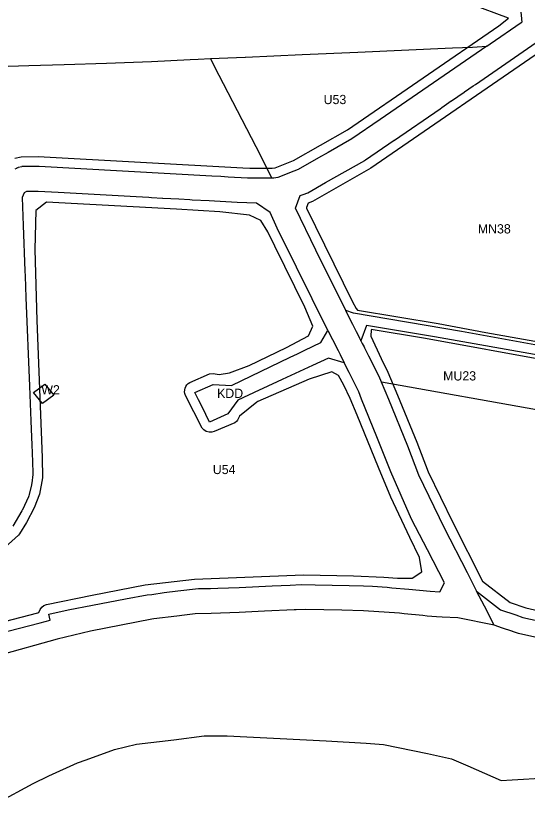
# Model space of a CAD drawing. Extents: x 7428103 to 7431580, y 5545880 to 5549002.
# Drawn here: x 7429910.1 to 7430217.3, y 5546647.9 to 5547123.1 of the extents above; entities that cross this region are included whole.
import ezdxf

# ---------------------------------------------------------------- set-up
doc = ezdxf.new("R2010")
doc.units = 0
for name, color, linetype in [('CZ_L_linie rozgraniczające tereny o różnym przeznaczeniu oraz różnych warunkach ich zabudowy i zagospodarowania', 7, 'Continuous'), ('CZ_L_maksymalne nieprzekraczalne linie zabudowy', 7, 'Continuous'), ('CZ_L_opisy_linie rozgraniczające tereny o różnym przeznaczeniu oraz różnych warunkach ich zabudowy i zagospodarowania', 7, 'Continuous')]:
    doc.layers.add(name, color=color, linetype=linetype)

msp = doc.modelspace()

# ---------------------------------------------------------------- linework, layer by layer
at = {"layer": 'CZ_L_linie rozgraniczające tereny o różnym przeznaczeniu oraz różnych warunkach ich zabudowy i zagospodarowania'}
for p, q in [((7430214.07, 5547121.48), (7430213.66, 5547125.26)), ((7430214.13, 5547120.94), (7430214.07, 5547121.48)), ((7430214.29, 5547119.51), (7430214.13, 5547120.94)), ((7430195.04, 5547106.24), (7430213.63, 5547119.05)), ((7430213.63, 5547119.05), (7430214.29, 5547119.51)), ((7430186.16, 5547081.91), (7430227.89, 5547110.67)), ((7430193.08, 5547104.9), (7430195.04, 5547106.24)), ((7430082.13, 5547099.87), (7430115.61, 5547101.33)), ((7430115.61, 5547101.33), (7430172.37, 5547103.82)), ((7430192.96, 5547104.82), (7430128.96, 5547060.72)), ((7430172.37, 5547103.82), (7430184.45, 5547104.35)), ((7430184.45, 5547104.35), (7430192.96, 5547104.82)), ((7430192.96, 5547104.82), (7430193.08, 5547104.9)), ((7429991.56, 5547095.77), (7430014.76, 5547096.83)), ((7430014.73, 5547096.88), (7430019.55, 5547097.14)), ((7430014.76, 5547096.83), (7430014.73, 5547096.88)), ((7430019.55, 5547097.14), (7430026.94, 5547097.46)), ((7430026.94, 5547097.46), (7430047.84, 5547098.37)), ((7430026.94, 5547097.46), (7430029.2, 5547092.87)), ((7430047.84, 5547098.37), (7430047.98, 5547098.37)), ((7430047.98, 5547098.37), (7430082.13, 5547099.87)), ((7429876.37, 5547092.06), (7429917.87, 5547093.18)), ((7429917.87, 5547093.18), (7429939.04, 5547093.84)), ((7429939.04, 5547093.84), (7429964.6, 5547094.63)), ((7429964.6, 5547094.63), (7429991.56, 5547095.77)), ((7430029.2, 5547092.87), (7430037.4, 5547077.05)), ((7430184.86, 5547081.02), (7430186.16, 5547081.91)), ((7430037.4, 5547077.05), (7430054.22, 5547044.6)), ((7430171.79, 5547072.03), (7430179.45, 5547077.3)), ((7430179.45, 5547077.3), (7430179.47, 5547077.31)), ((7430179.47, 5547077.31), (7430179.55, 5547077.36)), ((7430179.55, 5547077.36), (7430184.86, 5547081.02)), ((7430164.93, 5547067.29), (7430166.04, 5547068.05)), ((7430166.04, 5547068.05), (7430171.67, 5547071.93)), ((7430171.67, 5547071.93), (7430171.79, 5547072.03)), ((7430137.47, 5547048.36), (7430164.93, 5547067.29)), ((7430128.96, 5547060.72), (7430111.97, 5547049.08)), ((7430111.97, 5547049.08), (7430097.71, 5547040.99)), ((7430054.22, 5547044.6), (7430063.83, 5547025.55)), ((7430120.19, 5547036.53), (7430137.45, 5547048.35)), ((7430137.45, 5547048.35), (7430137.46, 5547048.35)), ((7430137.46, 5547048.35), (7430137.47, 5547048.36)), ((7430097.71, 5547040.99), (7430091.96, 5547037.73)), ((7430091.96, 5547037.73), (7430079.67, 5547030.76)), ((7430096.17, 5547022.87), (7430119.65, 5547036.19)), ((7430119.65, 5547036.19), (7430119.71, 5547036.24)), ((7430119.71, 5547036.24), (7430119.84, 5547036.32)), ((7430119.84, 5547036.32), (7430119.86, 5547036.33)), ((7430119.86, 5547036.33), (7430120.08, 5547036.46)), ((7430120.08, 5547036.46), (7430120.11, 5547036.48)), ((7430120.11, 5547036.48), (7430120.19, 5547036.53)), ((7429910.5, 5547031.42), (7429909.53, 5547030.84)), ((7429910.56, 5547031.45), (7429910.5, 5547031.42)), ((7429910.57, 5547031.46), (7429910.56, 5547031.45)), ((7429911.15, 5547031.77), (7429910.57, 5547031.46)), ((7429911.19, 5547031.78), (7429911.15, 5547031.77)), ((7429911.2, 5547031.79), (7429911.19, 5547031.78)), ((7429911.21, 5547031.8), (7429911.2, 5547031.79)), ((7429911.22, 5547031.81), (7429911.21, 5547031.8)), ((7429911.5, 5547031.91), (7429911.22, 5547031.81)), ((7429913.73, 5547032.44), (7429911.5, 5547031.91)), ((7429913.78, 5547032.45), (7429913.73, 5547032.44)), ((7429914.07, 5547032.5), (7429913.78, 5547032.45)), ((7429914.17, 5547032.49), (7429914.07, 5547032.5)), ((7429914.24, 5547032.5), (7429914.17, 5547032.49)), ((7429914.26, 5547032.5), (7429914.24, 5547032.5)), ((7429914.28, 5547032.5), (7429914.26, 5547032.5)), ((7429923.55, 5547032.61), (7429914.28, 5547032.5)), ((7429923.58, 5547032.61), (7429923.55, 5547032.61)), ((7429923.6, 5547032.6), (7429923.58, 5547032.61)), ((7429923.61, 5547032.61), (7429923.6, 5547032.6)), ((7429923.63, 5547032.61), (7429923.61, 5547032.61)), ((7429923.65, 5547032.61), (7429923.63, 5547032.61)), ((7429923.99, 5547032.6), (7429923.65, 5547032.61)), ((7429924, 5547032.6), (7429923.99, 5547032.6)), ((7429924.06, 5547032.6), (7429924, 5547032.6)), ((7430027.9, 5547026.75), (7429924.06, 5547032.6)), ((7430077.06, 5547029.67), (7430067.54, 5547025.98)), ((7430079.66, 5547030.75), (7430077.06, 5547029.67)), ((7430079.67, 5547030.76), (7430079.66, 5547030.75)), ((7430033.22, 5547026.45), (7430027.9, 5547026.75)), ((7430037.55, 5547026.21), (7430033.22, 5547026.45)), ((7430049.34, 5547025.55), (7430037.55, 5547026.21)), ((7430049.38, 5547025.54), (7430049.34, 5547025.55)), ((7430063.83, 5547025.55), (7430049.38, 5547025.54)), ((7430065.12, 5547025.55), (7430063.83, 5547025.55)), ((7430067.54, 5547025.98), (7430065.12, 5547025.55)), ((7430085.45, 5547016.79), (7430096.17, 5547022.87)), ((7429915.08, 5547016.67), (7429913.85, 5547013.94)), ((7429916.5, 5547017.53), (7429915.08, 5547016.67)), ((7429923.47, 5547017.61), (7429916.5, 5547017.53)), ((7429935.42, 5547016.94), (7429923.47, 5547017.61)), ((7429982.3, 5547014.3), (7429935.42, 5547016.94)), ((7430080.91, 5547015.06), (7430082.71, 5547015.78)), ((7430082.71, 5547015.78), (7430085.42, 5547016.77)), ((7430085.42, 5547016.77), (7430085.45, 5547016.79)), ((7429913.85, 5547013.94), (7429914.5, 5546997.16)), ((7429990.05, 5547013.86), (7429982.3, 5547014.3)), ((7429991.68, 5547013.77), (7429990.05, 5547013.86)), ((7429998.21, 5547013.4), (7429991.68, 5547013.77)), ((7429998.32, 5547013.38), (7429998.21, 5547013.4)), ((7430007.94, 5547012.84), (7429998.32, 5547013.38)), ((7430008.08, 5547012.84), (7430007.94, 5547012.84)), ((7430008.09, 5547012.85), (7430008.08, 5547012.84)), ((7430014.65, 5547012.48), (7430008.09, 5547012.85)), ((7430015.98, 5547012.4), (7430014.65, 5547012.48)), ((7430026.16, 5547011.83), (7430015.98, 5547012.4)), ((7430029.43, 5547011.64), (7430026.16, 5547011.83)), ((7430043.05, 5547010.88), (7430029.43, 5547011.64)), ((7430054.67, 5547010.42), (7430043.05, 5547010.88)), ((7430078.03, 5547007.45), (7430080.91, 5547015.06)), ((7430062.88, 5547004.79), (7430054.67, 5547010.42)), ((7430090.32, 5546982.18), (7430078.03, 5547007.45)), ((7430067.03, 5546995.38), (7430062.88, 5547004.79)), ((7429914.5, 5546997.16), (7429915.56, 5546969.84)), ((7430078.67, 5546971.92), (7430067.03, 5546995.38)), ((7430106.9, 5546948.83), (7430090.32, 5546982.18)), ((7429915.56, 5546969.84), (7429915.69, 5546966.56)), ((7430097.58, 5546934.01), (7430078.67, 5546971.92)), ((7429915.69, 5546966.56), (7429916.18, 5546953.87)), ((7429916.18, 5546953.87), (7429918.25, 5546900.55)), ((7430108.26, 5546946.1), (7430106.9, 5546948.83)), ((7430108.29, 5546946.04), (7430108.26, 5546946.1)), ((7430111.58, 5546939.45), (7430108.29, 5546946.04)), ((7430112.94, 5546944.31), (7430108.29, 5546946.04)), ((7430177.87, 5546933.33), (7430112.94, 5546944.31)), ((7430112.57, 5546937.47), (7430111.58, 5546939.45)), ((7430113.7, 5546935.2), (7430112.57, 5546937.47)), ((7430114.74, 5546933.12), (7430113.7, 5546935.2)), ((7430120.69, 5546936.95), (7430117.39, 5546927.81)), ((7430161.61, 5546930.19), (7430120.69, 5546936.95)), ((7430093.22, 5546926.67), (7430097.58, 5546934.01)), ((7430097.58, 5546934.01), (7430100.29, 5546928.57)), ((7430115.47, 5546931.65), (7430114.74, 5546933.12)), ((7430116.7, 5546929.2), (7430115.47, 5546931.65)), ((7430271.15, 5546910.68), (7430161.61, 5546930.19)), ((7430228.48, 5546924.09), (7430177.87, 5546933.33)), ((7430083.62, 5546922.03), (7430093.22, 5546926.67)), ((7430100.29, 5546928.57), (7430103.63, 5546921.89)), ((7430117.33, 5546927.94), (7430116.7, 5546929.2)), ((7430117.39, 5546927.81), (7430117.33, 5546927.94)), ((7430117.39, 5546927.81), (7430118.21, 5546926.18)), ((7430118.21, 5546926.18), (7430119.28, 5546924.05)), ((7430079.3, 5546919.94), (7430083.62, 5546922.03)), ((7430103.63, 5546921.89), (7430104.83, 5546919.49)), ((7430119.28, 5546924.05), (7430119.55, 5546923.52)), ((7430119.55, 5546923.52), (7430120.8, 5546921.04)), ((7430120.8, 5546921.04), (7430121.95, 5546918.75)), ((7430039.66, 5546900.79), (7430074.97, 5546917.85)), ((7430074.97, 5546917.85), (7430079.3, 5546919.94)), ((7430097.86, 5546917.23), (7430088.26, 5546912.8)), ((7430107.35, 5546914.43), (7430097.86, 5546917.23)), ((7430104.83, 5546919.49), (7430107.35, 5546914.43)), ((7430121.95, 5546918.75), (7430128.07, 5546906.56)), ((7430088.26, 5546912.8), (7430070.05, 5546904.42)), ((7430110.24, 5546908.63), (7430107.35, 5546914.43)), ((7430116.1, 5546896.98), (7430110.24, 5546908.63)), ((7430128.07, 5546906.56), (7430129.53, 5546903.08)), ((7429920.78, 5546896.73), (7429927.49, 5546901.71)), ((7429927.49, 5546901.71), (7429932.96, 5546895.13)), ((7430017.67, 5546896.68), (7430028.68, 5546901.46)), ((7430028.68, 5546901.46), (7430039.66, 5546900.79)), ((7430070.05, 5546904.42), (7430058.53, 5546899.11)), ((7430129.53, 5546903.08), (7430129.8, 5546903.11)), ((7430129.53, 5546903.08), (7430133.9, 5546892.72)), ((7430129.8, 5546903.11), (7430285.61, 5546875.17)), ((7429918.25, 5546900.55), (7429919.06, 5546879.69)), ((7429926.08, 5546890.04), (7429920.78, 5546896.73)), ((7430019.89, 5546892.2), (7430017.67, 5546896.68)), ((7430056.31, 5546898.09), (7430043.41, 5546892.15)), ((7430058.53, 5546899.11), (7430056.31, 5546898.09)), ((7430117.83, 5546892.59), (7430116.1, 5546896.98)), ((7429932.96, 5546895.13), (7429926.08, 5546890.04)), ((7430023.73, 5546884.42), (7430019.89, 5546892.2)), ((7430043.41, 5546892.15), (7430037.36, 5546883.92)), ((7430126.99, 5546869.99), (7430117.83, 5546892.59)), ((7430133.9, 5546892.72), (7430145.33, 5546864.5)), ((7430024.25, 5546883.37), (7430023.73, 5546884.42)), ((7430026.46, 5546878.89), (7430024.25, 5546883.37)), ((7430037.36, 5546883.92), (7430026.46, 5546878.89)), ((7429919.06, 5546879.69), (7429919.63, 5546865.01)), ((7430135.35, 5546848.88), (7430126.99, 5546869.99)), ((7429919.63, 5546865.01), (7429919.82, 5546860.5)), ((7430145.33, 5546864.5), (7430152.06, 5546847.07)), ((7429919.82, 5546860.5), (7429920.3, 5546848.5)), ((7430147.8, 5546820.44), (7430135.35, 5546848.88)), ((7429920.27, 5546847.38), (7429919.69, 5546842.06)), ((7429920.3, 5546848.39), (7429920.27, 5546847.5)), ((7429920.27, 5546847.5), (7429920.27, 5546847.47)), ((7429920.27, 5546847.47), (7429920.27, 5546847.38)), ((7429920.3, 5546848.5), (7429920.29, 5546848.44)), ((7429920.29, 5546848.44), (7429920.3, 5546848.39)), ((7430152.06, 5546847.07), (7430167.46, 5546815.24)), ((7429919.53, 5546841.15), (7429918.17, 5546835.41)), ((7429919.54, 5546841.25), (7429919.53, 5546841.15)), ((7429919.56, 5546841.36), (7429919.54, 5546841.25)), ((7429919.59, 5546841.58), (7429919.56, 5546841.36)), ((7429919.66, 5546841.88), (7429919.59, 5546841.58)), ((7429919.69, 5546842.06), (7429919.66, 5546841.97)), ((7429919.66, 5546841.97), (7429919.66, 5546841.88)), ((7429917.94, 5546834.63), (7429917.91, 5546834.56)), ((7429918.15, 5546835.32), (7429917.94, 5546834.63)), ((7429918.17, 5546835.41), (7429918.15, 5546835.34)), ((7429918.15, 5546835.34), (7429918.15, 5546835.32)), ((7429917.67, 5546833.96), (7429914.02, 5546826.13)), ((7429917.69, 5546834.01), (7429917.67, 5546833.96)), ((7429917.7, 5546834.01), (7429917.69, 5546834.01)), ((7429917.89, 5546834.48), (7429917.7, 5546834.01)), ((7429917.91, 5546834.56), (7429917.89, 5546834.48)), ((7429913.68, 5546825.49), (7429908.23, 5546816.26)), ((7429913.72, 5546825.57), (7429913.68, 5546825.49)), ((7429913.74, 5546825.61), (7429913.72, 5546825.57)), ((7429913.87, 5546825.88), (7429913.74, 5546825.61)), ((7429913.9, 5546825.93), (7429913.87, 5546825.88)), ((7429913.97, 5546826.06), (7429913.9, 5546825.93)), ((7429914.02, 5546826.13), (7429913.97, 5546826.06)), ((7430157.37, 5546802.04), (7430147.8, 5546820.44)), ((7430167.46, 5546815.24), (7430181.24, 5546788.43)), ((7430167.63, 5546782.15), (7430157.37, 5546802.04)), ((7430181.24, 5546788.43), (7430185.95, 5546778.91)), ((7430007.39, 5546777.39), (7430019.74, 5546778.73)), ((7430019.74, 5546778.73), (7430027.07, 5546778.86)), ((7430027.07, 5546778.86), (7430031.35, 5546778.93)), ((7430031.35, 5546778.93), (7430031.4, 5546778.99)), ((7430031.4, 5546778.99), (7430031.4, 5546779)), ((7430031.4, 5546779), (7430031.42, 5546778.99)), ((7430031.42, 5546778.99), (7430031.46, 5546778.97)), ((7430031.46, 5546778.97), (7430044.26, 5546779.5)), ((7430031.46, 5546778.97), (7430031.46, 5546778.97)), ((7430044.26, 5546779.5), (7430064.16, 5546780.38)), ((7430064.16, 5546780.38), (7430074.91, 5546780.85)), ((7430074.91, 5546780.85), (7430081.47, 5546781.17)), ((7430081.47, 5546781.17), (7430089.85, 5546781.04)), ((7430089.85, 5546781.04), (7430110.23, 5546780.6)), ((7430110.23, 5546780.6), (7430118.99, 5546780.35)), ((7430118.99, 5546780.35), (7430124.29, 5546780.2)), ((7430124.29, 5546780.2), (7430133.25, 5546779.55)), ((7430133.25, 5546779.55), (7430135.99, 5546779.3)), ((7430135.99, 5546779.3), (7430146.13, 5546778.37)), ((7430146.13, 5546778.37), (7430146.17, 5546778.43)), ((7430146.17, 5546778.43), (7430158.95, 5546777.17)), ((7430164.89, 5546776.82), (7430167.63, 5546782.15)), ((7430185.95, 5546778.91), (7430186.82, 5546777.24)), ((7429975.9, 5546772.55), (7429988.92, 5546775.05)), ((7429988.92, 5546775.05), (7429991.74, 5546775.29)), ((7429991.74, 5546775.29), (7429999.18, 5546776.35)), ((7429999.18, 5546776.35), (7429999.21, 5546776.38)), ((7429999.21, 5546776.38), (7430007.39, 5546777.39)), ((7430158.95, 5546777.17), (7430158.96, 5546777.16)), ((7430158.96, 5546777.16), (7430159.08, 5546777.14)), ((7430159.08, 5546777.14), (7430164.89, 5546776.82)), ((7430191.53, 5546768.15), (7430186.82, 5546777.24)), ((7430186.82, 5546777.24), (7430201.15, 5546766.04)), ((7429941.52, 5546766.02), (7429956.23, 5546768.87)), ((7429956.23, 5546768.87), (7429975.9, 5546772.55)), ((7430197.47, 5546756.72), (7430191.53, 5546768.15)), ((7429929.91, 5546763.48), (7429941.52, 5546766.02)), ((7429930.76, 5546759.74), (7429929.91, 5546763.48)), ((7430017.75, 5546763.64), (7430011.31, 5546762.83)), ((7430017.77, 5546763.63), (7430017.75, 5546763.64)), ((7430027.51, 5546763.8), (7430017.77, 5546763.63)), ((7430044.23, 5546764.43), (7430027.51, 5546763.8)), ((7430059.41, 5546765.15), (7430044.23, 5546764.43)), ((7430077.29, 5546765.97), (7430059.41, 5546765.15)), ((7430077.6, 5546766.07), (7430077.29, 5546765.97)), ((7430078.46, 5546766.08), (7430077.6, 5546766.07)), ((7430084.37, 5546766.15), (7430078.46, 5546766.08)), ((7430105.87, 5546765.72), (7430084.37, 5546766.15)), ((7430118.88, 5546765.35), (7430105.87, 5546765.72)), ((7430140.51, 5546763.94), (7430118.88, 5546765.35)), ((7430143.37, 5546763.65), (7430140.51, 5546763.94)), ((7430154.66, 5546762.5), (7430143.37, 5546763.65)), ((7430201.15, 5546766.04), (7430210.55, 5546762.9)), ((7429924.76, 5546758.19), (7429930.76, 5546759.74)), ((7429991.84, 5546760.34), (7429954.86, 5546753.22)), ((7429992.94, 5546760.55), (7429991.84, 5546760.34)), ((7430006.8, 5546762.27), (7429992.94, 5546760.55)), ((7430011.31, 5546762.83), (7430006.8, 5546762.27)), ((7430157.24, 5546762.28), (7430154.66, 5546762.5)), ((7430162.71, 5546761.81), (7430157.24, 5546762.28)), ((7430166.19, 5546761.65), (7430162.71, 5546761.81)), ((7430166.25, 5546761.65), (7430166.19, 5546761.65)), ((7430175.63, 5546761.22), (7430166.25, 5546761.65)), ((7430197.47, 5546756.72), (7430175.63, 5546761.22)), ((7430210.55, 5546762.9), (7430214.71, 5546761.39)), ((7430214.71, 5546761.39), (7430232.33, 5546757.46)), ((7429886.04, 5546748.22), (7429924.76, 5546758.19)), ((7430197.48, 5546756.72), (7430197.47, 5546756.72)), ((7430202.46, 5546755.06), (7430197.48, 5546756.72)), ((7430208.06, 5546753.2), (7430202.46, 5546755.06)), ((7429954.86, 5546753.22), (7429934.88, 5546748.35)), ((7430208.15, 5546753.2), (7430208.06, 5546753.2)), ((7430208.35, 5546753.03), (7430208.15, 5546753.2)), ((7430210.94, 5546752.12), (7430208.35, 5546753.03)), ((7430211.96, 5546751.76), (7430210.94, 5546752.12)), ((7430223.76, 5546749.13), (7430211.96, 5546751.76)), ((7429934.88, 5546748.35), (7429882.96, 5546733.84)), ((7429982.59, 5546685.3), (7430004.97, 5546687.75)), ((7430004.97, 5546687.75), (7430023.22, 5546690.22)), ((7430023.22, 5546690.22), (7430036.94, 5546690.19)), ((7430036.94, 5546690.19), (7430048.86, 5546689.62)), ((7430048.86, 5546689.62), (7430068.87, 5546688.59)), ((7430068.87, 5546688.59), (7430096.53, 5546687.2)), ((7429969.41, 5546682.02), (7429982.59, 5546685.3)), ((7430096.53, 5546687.2), (7430120.58, 5546685.75)), ((7430120.58, 5546685.75), (7430130.99, 5546684.94)), ((7430130.99, 5546684.94), (7430157.41, 5546679.68)), ((7429952.26, 5546675.84), (7429969.41, 5546682.02)), ((7430157.41, 5546679.68), (7430171.85, 5546676.48)), ((7429930, 5546666.21), (7429947.09, 5546673.98)), ((7429947.09, 5546673.98), (7429952.26, 5546675.84)), ((7430171.85, 5546676.48), (7430181.64, 5546672.3)), ((7430181.64, 5546672.3), (7430201.7, 5546663.46)), ((7429920.47, 5546661.62), (7429930, 5546666.21)), ((7430201.7, 5546663.46), (7430208.25, 5546663.85)), ((7430208.25, 5546663.85), (7430208.3, 5546663.85)), ((7430208.3, 5546663.85), (7430238.8, 5546665.66)), ((7429895.22, 5546647.94), (7429920.47, 5546661.62))]:
    msp.add_line(p, q, dxfattribs=at)
at = {"layer": 'CZ_L_maksymalne nieprzekraczalne linie zabudowy'}
for points in [[(7429909.53, 5547037.57), (7429913.23, 5547038.44), (7429923.48, 5547038.61), (7430046.46, 5547031.72), (7430050.67, 5547031.54), (7430064.11, 5547031.55), (7430065.87, 5547031.78), (7430076.9, 5547036.1), (7430109.4, 5547054.59), (7430200.23, 5547117.11), (7430206.1, 5547121.66), (7430183.43, 5547130.1)], [(7430231.7, 5547106), (7430123.4, 5547031.46), (7430088.38, 5547011.55), (7430085.68, 5547010.48), (7430084.65, 5547007.98), (7430084.68, 5547007.5), (7430095.42, 5546985.4), (7430112.43, 5546951.18), (7430114.48, 5546947.07), (7430115.24, 5546946.15), (7430163.72, 5546938.19), (7430192.49, 5546932.83), (7430263.64, 5546920.06), (7430270.09, 5546922.66)], [(7429852.92, 5546745.87), (7429923.38, 5546764.18), (7429923.99, 5546764.48), (7429924.61, 5546766.29), (7429925.63, 5546767.69), (7429926.85, 5546768.64), (7429928.43, 5546769.29), (7429955.96, 5546774.9), (7429987.86, 5546780.95), (7430017.33, 5546784.5), (7430082.85, 5546787.14), (7430112.9, 5546786.53), (7430131.1, 5546785.66), (7430139.4, 5546785.04), (7430148.18, 5546785.09), (7430154.03, 5546788.87), (7430152.59, 5546797.5), (7430146.74, 5546809.55), (7430135.4, 5546833.82), (7430127.86, 5546851.54), (7430115.15, 5546883.11), (7430110.94, 5546893.06), (7430107.17, 5546901.17), (7430103.9, 5546906.79), (7430099.89, 5546909.02), (7430086.31, 5546904.63), (7430055.53, 5546891.23), (7430054.85, 5546890.88), (7430044.45, 5546882.46), (7430043.34, 5546880.13), (7430042.59, 5546879.24), (7430041.69, 5546878.51), (7430029.21, 5546873.14), (7430027.73, 5546872.75), (7430026.18, 5546872.75), (7430024.51, 5546873.22), (7430023.05, 5546874.15), (7430022.01, 5546875.29), (7430012.02, 5546894.96), (7430011.64, 5546896.02), (7430011.46, 5546897.16), (7430011.73, 5546899.3), (7430012.16, 5546900.33), (7430012.8, 5546901.3), (7430013.62, 5546902.12), (7430014.58, 5546902.77), (7430026.49, 5546907.95), (7430028.6, 5546908.15), (7430032.25, 5546907.55), (7430038.54, 5546908.55), (7430050.26, 5546912.81), (7430072.69, 5546923.63), (7430085.96, 5546930.72), (7430088.48, 5546936.51), (7430083.66, 5546948.05), (7430065.76, 5546984.74), (7430061.49, 5546993.25), (7430057.3, 5547000.02), (7430050.36, 5547003.35), (7430032.69, 5547005.3), (7430006.58, 5547006.98), (7429928.52, 5547011.17), (7429922.09, 5547006.13), (7429921.48, 5546982.56), (7429922.76, 5546939.91), (7429925.93, 5546857.52), (7429926.05, 5546845.27), (7429924.37, 5546835.57), (7429921.16, 5546827.26), (7429916.52, 5546818.5), (7429912.32, 5546811.71), (7429911.59, 5546810.84), (7429903.68, 5546803.65)], [(7430123.61, 5546934.43), (7430123.25, 5546930.63), (7430129.53, 5546917.02), (7430133.6, 5546908.89), (7430139.45, 5546894.99), (7430150.9, 5546866.75), (7430157.78, 5546849.03), (7430172.51, 5546818.57), (7430190.46, 5546783.32), (7430206.96, 5546770.43), (7430216.39, 5546767.17), (7430255.6, 5546758.2)], [(7430230.85, 5546915.6), (7430156.13, 5546929.21), (7430123.59, 5546934.52)]]:
    msp.add_lwpolyline(points, dxfattribs=at)

# ---------------------------------------------------------------- texts
at = {"layer": 'CZ_L_opisy_linie rozgraniczające tereny o różnym przeznaczeniu oraz różnych warunkach ich zabudowy i zagospodarowania'}
for s, p in [('U53', (7430095, 5547070.05)), ('MN38', (7430187.62, 5546992.29)), ('MU23', (7430166.79, 5546903.89)), ('W2', (7429925.38, 5546895.52)), ('KDD', (7430030.99, 5546893.39)), ('U54', (7430028.41, 5546847.62))]:
    msp.add_text(s, height=5.549, dxfattribs=at).set_placement(p)

doc.saveas('drawing.dxf')
